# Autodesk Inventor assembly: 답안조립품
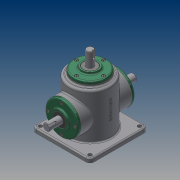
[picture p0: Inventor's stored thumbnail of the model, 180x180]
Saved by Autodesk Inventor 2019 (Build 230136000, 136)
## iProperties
Created: 2019-03
Part Number: 답안조립품
Material: 일반
Document SubType Name: Assembly
Designer: PC312-16
Author: PC312-16
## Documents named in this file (16)
- C:\Users\PC312-16\Desktop\490314V1004\답안조립품.iam
- C:\Users\PC312-16\Desktop\490314V1004\본체.ipt
- C:\Users\PC312-16\Desktop\490314V1004\커버.ipt
- C:\Users\PC312-16\Desktop\490314V1004\베어링 6203.ipt
- C:\Users\PC312-16\Desktop\490314V1004\오일 실.ipt
- 오일 실.ipt
- C:\Users\PC312-16\Desktop\490314V1004\메인 축.ipt
- 메인 축.ipt
- C:\Users\PC312-16\Desktop\490314V1004\서브 축.ipt
- 서브 축.ipt
- C:\Users\PC312-16\Desktop\490314V1004\키 5x5.ipt
- C:\Users\PC312-16\Desktop\490314V1004\키 4x4.ipt
- C:\Users\PC312-16\Desktop\490314V1004\메인 베벨기어.ipt
- C:\Users\PC312-16\Desktop\490314V1004\서브 베벨기어.ipt
- C:\Users\PC312-16\Desktop\490314V1004\볼트 M4.ipt
- 볼트 M4.ipt
